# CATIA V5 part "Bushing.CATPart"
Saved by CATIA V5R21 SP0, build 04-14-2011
Part number: Bushing
Bounding box of the stored display mesh (mm): x -13.45 to 13.45, y 0 to 63, z -13.45 to 13.45
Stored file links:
  D:\CATIA V5R21 E-RESOURCES\CATIA-V5R21\catia-v5r21-Prts\c12_catia_v5r21_prt\c12_catia_v5r21figr_12-49\Bushing.CATPart
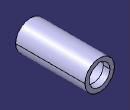
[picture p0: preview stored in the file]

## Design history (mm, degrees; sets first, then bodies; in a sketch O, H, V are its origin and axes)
Body1 (main body)
  Sketch1 on zx-plane, origin (0, 0, 0), H (-1, 0, 0), V (0, 0, 1)
    circle A1 centre (0, 0) radius 9.5
    circle A2 centre (0, 0) radius 13.45
    radius A1 = 9.5
    radius A2 = 13.45
  Pad1: profile Sketch1, direction (0, 1, 0), length 63
  Sketch2 on face of Pad1, origin (0, 63, 0), H (-1, 0, 0), V (0, 0, 1)
    line L1 (-1.5, 9.3808) -> (1.5, 9.3808)
    line L2 (1.5, 9.3808) -> (1.5, 10.1808)
    line L3 (1.5, 10.1808) -> (-1.5, 10.1808)
    line L4 (-1.5, 10.1808) -> (-1.5, 9.3808)
    point P2 (1.5, 9.3808)
    reference projected circle E1 centre (0, 0) radius 9.5 from edge of Pad1
    length L3 = 3
    length L2 = 0.8
    distance V L4 = 1.5
    horizontal: L1 H, L3 H
    vertical: L2 V, L4 V
    coincidence: P2 E1
  Pocket1: profile Sketch2, direction (0, -1, 0), through (limit type 6)
  Sketch3 on xy-plane, origin (0, 0, 0), H (1, 0, 0), V (0, 1, 0)
    line L1 (9.5, 57) -> (10.3, 57)
    line L2 (10.3, 57) -> (10.3, 49)
    line L3 (10.3, 49) -> (9.5, 49)
    line L4 (9.5, 49) -> (9.5, 57)
    reference projected line E1 (13.45, 63) -> (-13.45, 63) from edge of Pad1
    length L2 = 8
    length L1 = 0.8
    distance L3 E1 = 14
    distance V L4 = 9.5
    horizontal: L1 H, L3 H
    vertical: L2 V, L4 V
  Groove1: profile Sketch3, axis axis of face of Pad1, angle 360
